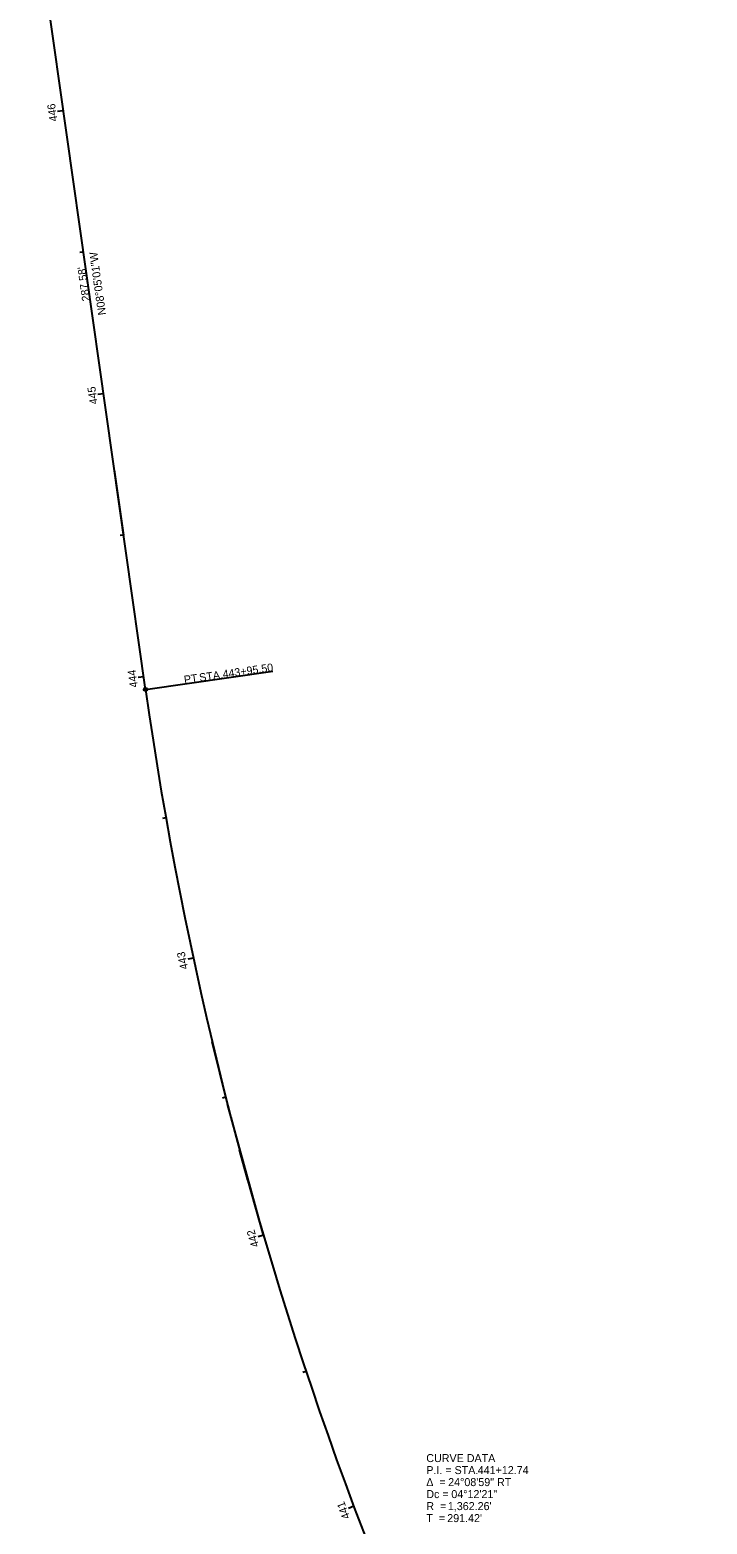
# Model space of a CAD drawing. Extents: x 124376 to 127490, y 510907 to 515083.
# Drawn here: x 127024 to 127261, y 511427 to 511950 of the extents above; entities that cross this region are included whole.
import ezdxf

# ---------------------------------------------------------------- set-up
doc = ezdxf.new("R2010")
doc.units = 0
for name, color, linetype in [('Default', 7, 'Continuous'), ('RW_X_CL', 7, 'Continuous'), ('RW_X_CL_100_Bearings', 7, 'Continuous'), ('RW_X_CL_100_Cardinal_Points', 7, 'Continuous'), ('RW_X_CL_100_Curve_Data', 7, 'Continuous'), ('RW_X_CL_100_Distances', 7, 'Continuous'), ('RW_X_CL_100_Stations', 7, 'Continuous'), ('SC_Scratch1', 7, 'Continuous')]:
    doc.layers.add(name, color=color, linetype=linetype)

msp = doc.modelspace()

# ---------------------------------------------------------------- linework, layer by layer
at = {"layer": 'Default'}
for p, q in [((127064.82, 511719.28), (127024.38, 512004)), ((127053.91, 511796.11), (127057.15, 511773.24)), ((127106.08, 511528.36), (127097.97, 511557.24))]:
    msp.add_line(p, q, dxfattribs=at)
msp.add_arc((128413.54, 511910.84), 1362.26, 188.08366, 212.23338, dxfattribs=at)
at = {"layer": 'RW_X_CL'}
msp.add_line((127064.82, 511719.28), (127024.38, 512004), dxfattribs=at)
msp.add_arc((128413.54, 511910.84), 1362.26, 188.08366, 212.23338, dxfattribs=at)
at = {"layer": 'RW_X_CL_100_Cardinal_Points'}
msp.add_line((127064.82, 511719.28), (127109.37, 511725.61), dxfattribs=at)
msp.add_circle((127064.82, 511719.28), 0.6, dxfattribs=at)
at = {"layer": 'RW_X_CL_100_Stations'}
for p, q in [((127036.06, 511921.75), (127034.08, 511921.47)), ((127043.09, 511872.25), (127041.9, 511872.08)), ((127050.12, 511822.74), (127048.14, 511822.46)), ((127057.15, 511773.24), (127055.97, 511773.07)), ((127064.19, 511723.74), (127062.2, 511723.46)), ((127071.97, 511674.35), (127070.79, 511674.14)), ((127081.55, 511625.28), (127079.59, 511624.86)), ((127092.92, 511576.59), (127091.76, 511576.3)), ((127106.08, 511528.36), (127104.16, 511527.8)), ((127121, 511480.64), (127119.86, 511480.26)), ((127137.65, 511433.5), (127135.78, 511432.79))]:
    msp.add_line(p, q, dxfattribs=at)
at = {"layer": 'SC_Scratch1'}
for p, q in [((127093.39, 511574.75), (127088.16, 511596.02)), ((127106.08, 511528.36), (127093.53, 511574.23)), ((127100.61, 511547.59), (127097.71, 511558.21))]:
    msp.add_line(p, q, dxfattribs=at)

# ---------------------------------------------------------------- texts
at = {"layer": 'RW_X_CL_100_Bearings'}
msp.add_text('N08°05\'01"W', height=2.8, rotation=98.0837, dxfattribs=at).set_placement((127051.04, 511850.41))
at = {"layer": 'RW_X_CL_100_Cardinal_Points'}
for s, p in [('PT', (127078.46, 511721.26)), (' STA. ', (127082.77, 511721.87)), ('443+95.50', (127092, 511723.18))]:
    msp.add_text(s, height=2.8, rotation=8.0837, dxfattribs=at).set_placement(p)
at = {"layer": 'RW_X_CL_100_Curve_Data'}
for s, p in [('CURVE DATA', (127163.02, 511448.97)), ('P.I. = STA. ', (127163.02, 511444.77)), ('441+12.74', (127181.01, 511444.77)), ('Δ  = ', (127163.02, 511440.57)), ('24°08\'59" RT', (127170.67, 511440.57)), ('Dc = ', (127163.02, 511436.37)), ('04°12\'21"', (127171.77, 511436.37)), ('R  = ', (127163.02, 511432.17)), ("1,362.26'", (127170.56, 511432.17)), ('T  = ', (127163.02, 511427.97)), ("291.42'", (127170.34, 511427.97))]:
    msp.add_text(s, height=2.8, dxfattribs=at).set_placement(p)
at = {"layer": 'RW_X_CL_100_Distances'}
msp.add_text("287.58'", height=2.8, rotation=98.0837, dxfattribs=at).set_placement((127045.47, 511855.26))
at = {"layer": 'RW_X_CL_100_Stations'}
for s, rotation, p in [('446', 98.0837, (127034.04, 511918.18)), ('445', 98.0837, (127048.1, 511819.22)), ('444', 98.0837, (127062.17, 511720.14)), ('443', 102.1003, (127079.77, 511621.63)), ('442', 106.3063, (127104.58, 511524.57)), ('441', 110.5122, (127136.44, 511429.6))]:
    msp.add_text(s, height=2.8, rotation=rotation, dxfattribs=at).set_placement(p)

doc.saveas('drawing.dxf')
